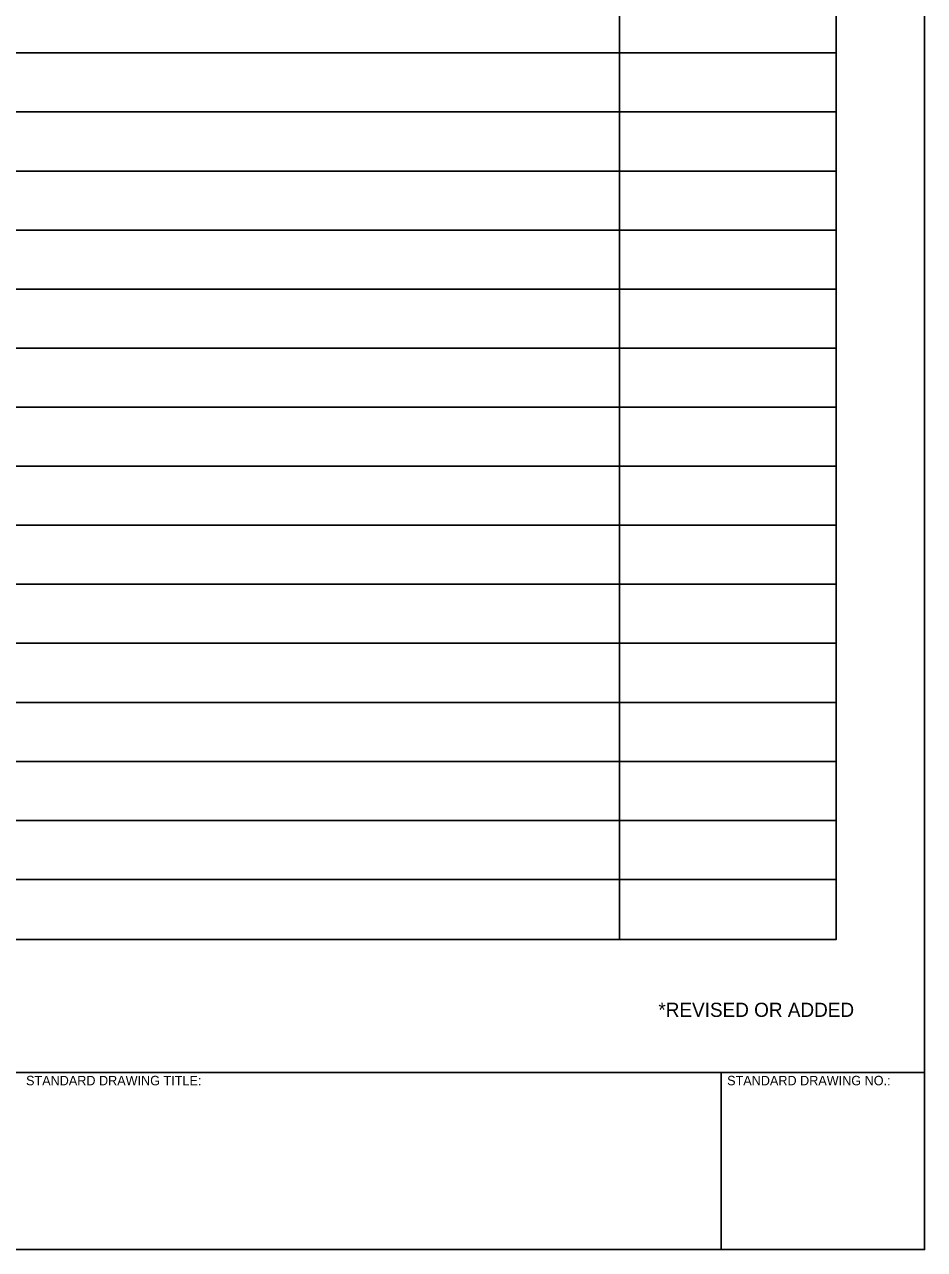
# Model space of a CAD drawing. Extents: x 0 to 5.28, y 0 to 1.73.
# Drawn here: x 2.01 to 2.646, y 0 to 0.865 of the extents above; entities that cross this region are included whole.
import ezdxf

# ---------------------------------------------------------------- set-up
doc = ezdxf.new("R2010")
doc.units = 0
for name, color, linetype in [('CT_Border_Perimeter_Shape', 7, 'Continuous'), ('CT_Dimensions', 7, 'Continuous'), ('CT_List_of _Standards', 7, 'Continuous'), ('CT_Title_Block_Linework', 7, 'Continuous'), ('CT_Title_Block_Text', 7, 'Continuous')]:
    doc.layers.add(name, color=color, linetype=linetype)

msp = doc.modelspace()

# ---------------------------------------------------------------- linework, layer by layer
at = {"layer": 'CT_Border_Perimeter_Shape'}
msp.add_lwpolyline([(0, 0), (2.64583, 0), (2.64583, 1.72917), (0, 1.72917)], close=True, dxfattribs=at)
at = {"layer": 'CT_Dimensions'}
msp.add_lwpolyline([(1.31463, 1.66667), (2.58342, 1.66667), (2.58342, 0.21875), (1.31463, 0.21875)], close=True, dxfattribs=at)
msp.add_lwpolyline([(1.31463, 1.66667), (2.58342, 1.66667), (2.58342, 0.21875), (1.31463, 0.21875)], close=True, dxfattribs=at)
at = {"layer": 'CT_List_of _Standards'}
for p, q in [((2.43047, 1.66667), (2.43047, 0.21875)), ((1.31463, 0.8445), (2.58342, 0.8445)), ((1.31463, 0.8445), (2.58342, 0.8445)), ((1.31463, 0.80283), (2.58342, 0.80283)), ((1.31463, 0.76116), (2.58342, 0.76116)), ((1.31463, 0.76116), (2.58342, 0.76116)), ((1.31463, 0.76116), (2.58342, 0.76116)), ((1.31463, 0.7195), (2.58342, 0.7195)), ((1.31463, 0.7195), (2.58342, 0.7195)), ((1.31463, 0.67783), (2.58342, 0.67783)), ((1.31463, 0.67783), (2.58342, 0.67783)), ((1.31463, 0.63616), (2.58342, 0.63616)), ((1.31463, 0.63616), (2.58342, 0.63616)), ((1.31463, 0.5945), (2.58342, 0.5945)), ((1.31463, 0.5945), (2.58342, 0.5945)), ((1.31463, 0.55283), (2.58342, 0.55283)), ((1.31463, 0.55283), (2.58342, 0.55283)), ((1.31463, 0.51116), (2.58342, 0.51116)), ((1.31463, 0.51116), (2.58342, 0.51116)), ((1.31463, 0.4695), (2.58342, 0.4695)), ((1.31463, 0.4695), (2.58342, 0.4695)), ((1.31463, 0.42783), (2.58342, 0.42783)), ((1.31463, 0.42783), (2.58342, 0.42783)), ((1.31463, 0.38616), (2.58342, 0.38616)), ((1.31463, 0.38616), (2.58342, 0.38616)), ((1.31463, 0.38616), (2.58342, 0.38616)), ((1.31463, 0.3445), (2.58342, 0.3445)), ((1.31463, 0.3445), (2.58342, 0.3445)), ((1.31463, 0.30283), (2.58342, 0.30283)), ((1.31463, 0.30283), (2.58342, 0.30283)), ((1.31463, 0.26116), (2.58342, 0.26116)), ((1.31463, 0.26116), (2.58342, 0.26116))]:
    msp.add_line(p, q, dxfattribs=at)
at = {"layer": 'CT_Title_Block_Linework'}
for p, q in [((2.64583, 0.125), (0, 0.125)), ((2.50225, 0.125), (2.50225, 0))]:
    msp.add_line(p, q, dxfattribs=at)

# ---------------------------------------------------------------- texts
at = {"layer": 'CT_Dimensions'}
msp.add_text('*REVISED OR ADDED', height=0.01, dxfattribs=at).set_placement((2.4579, 0.16417))
at = {"layer": 'CT_Title_Block_Text'}
for s, p in [('STANDARD DRAWING TITLE:', (2.01137, 0.11589)), ('STANDARD DRAWING NO.:', (2.50646, 0.11589))]:
    msp.add_text(s, height=0.0066667, dxfattribs=at).set_placement(p)

doc.saveas('drawing.dxf')
